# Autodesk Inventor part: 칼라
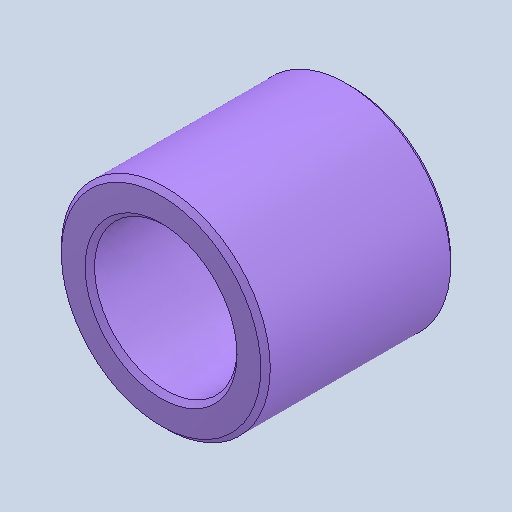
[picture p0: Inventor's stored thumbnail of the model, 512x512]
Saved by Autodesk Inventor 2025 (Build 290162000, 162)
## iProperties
Created: 2024-07
Part Number: 칼라
Material: 스테인리스강
Document SubType Name: Modeling
Designer: deana
Density: 8.08 g/cm^3
Appearance: 기본값
Author: jhkim
Sending System: Autodesk Inventor 2025
Preprocessor: ST-DEVELOPER v20
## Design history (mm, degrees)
feature "솔리드1"
node "솔리드2"
